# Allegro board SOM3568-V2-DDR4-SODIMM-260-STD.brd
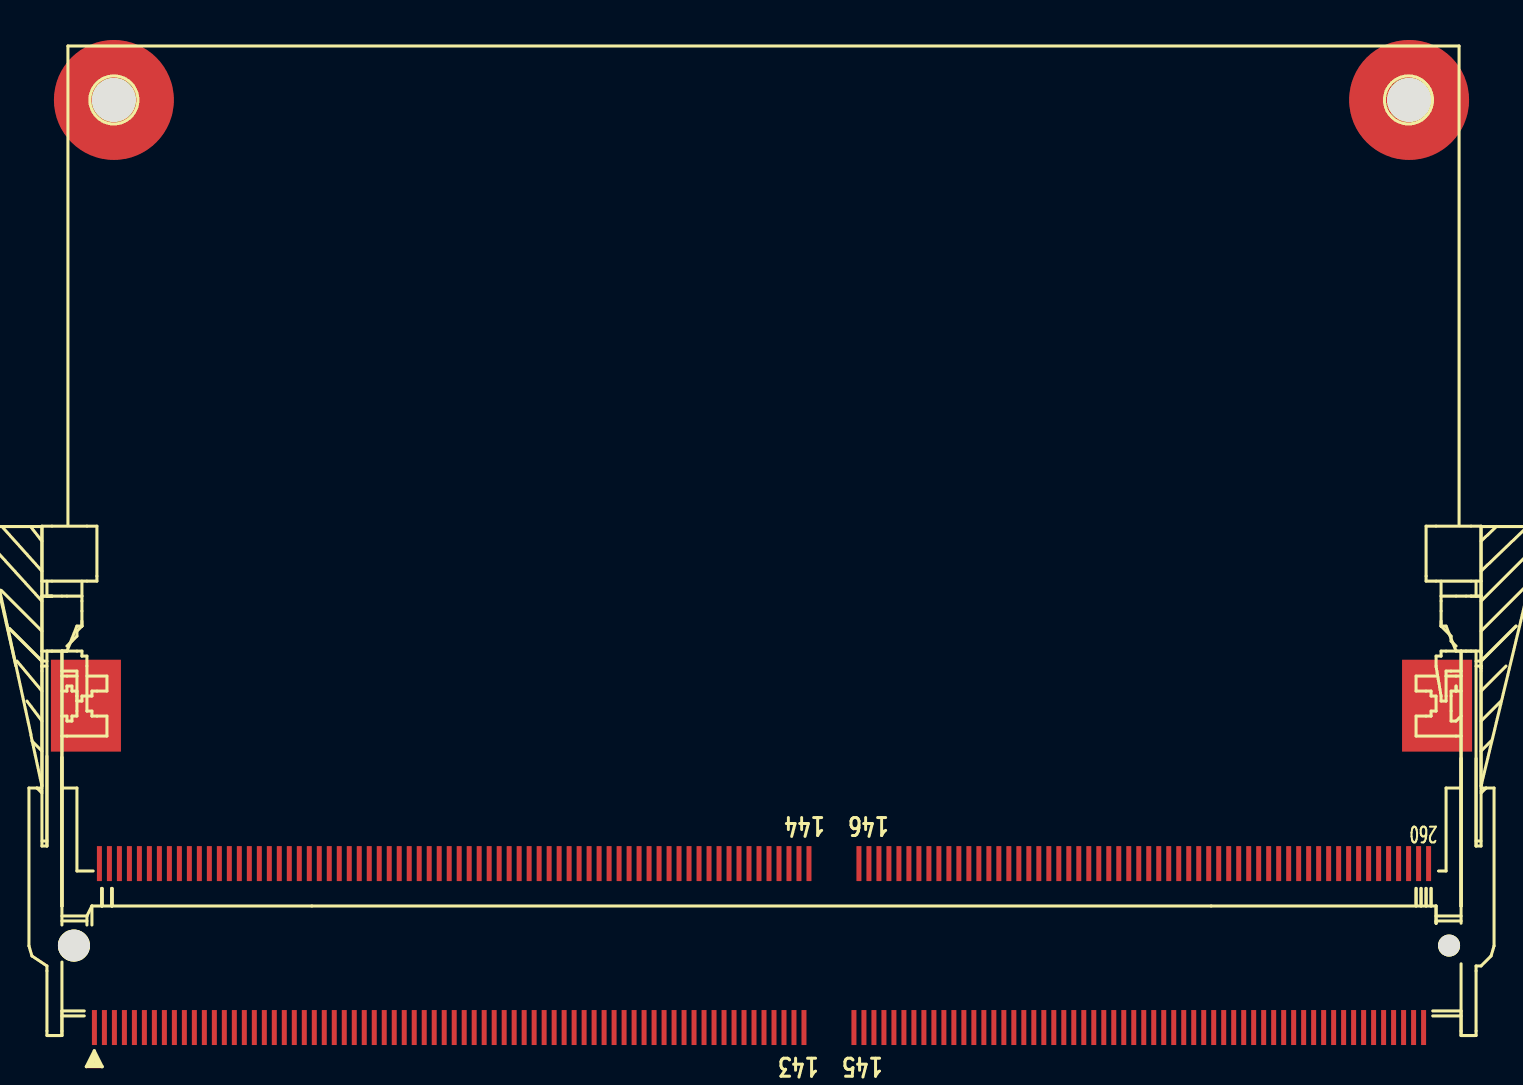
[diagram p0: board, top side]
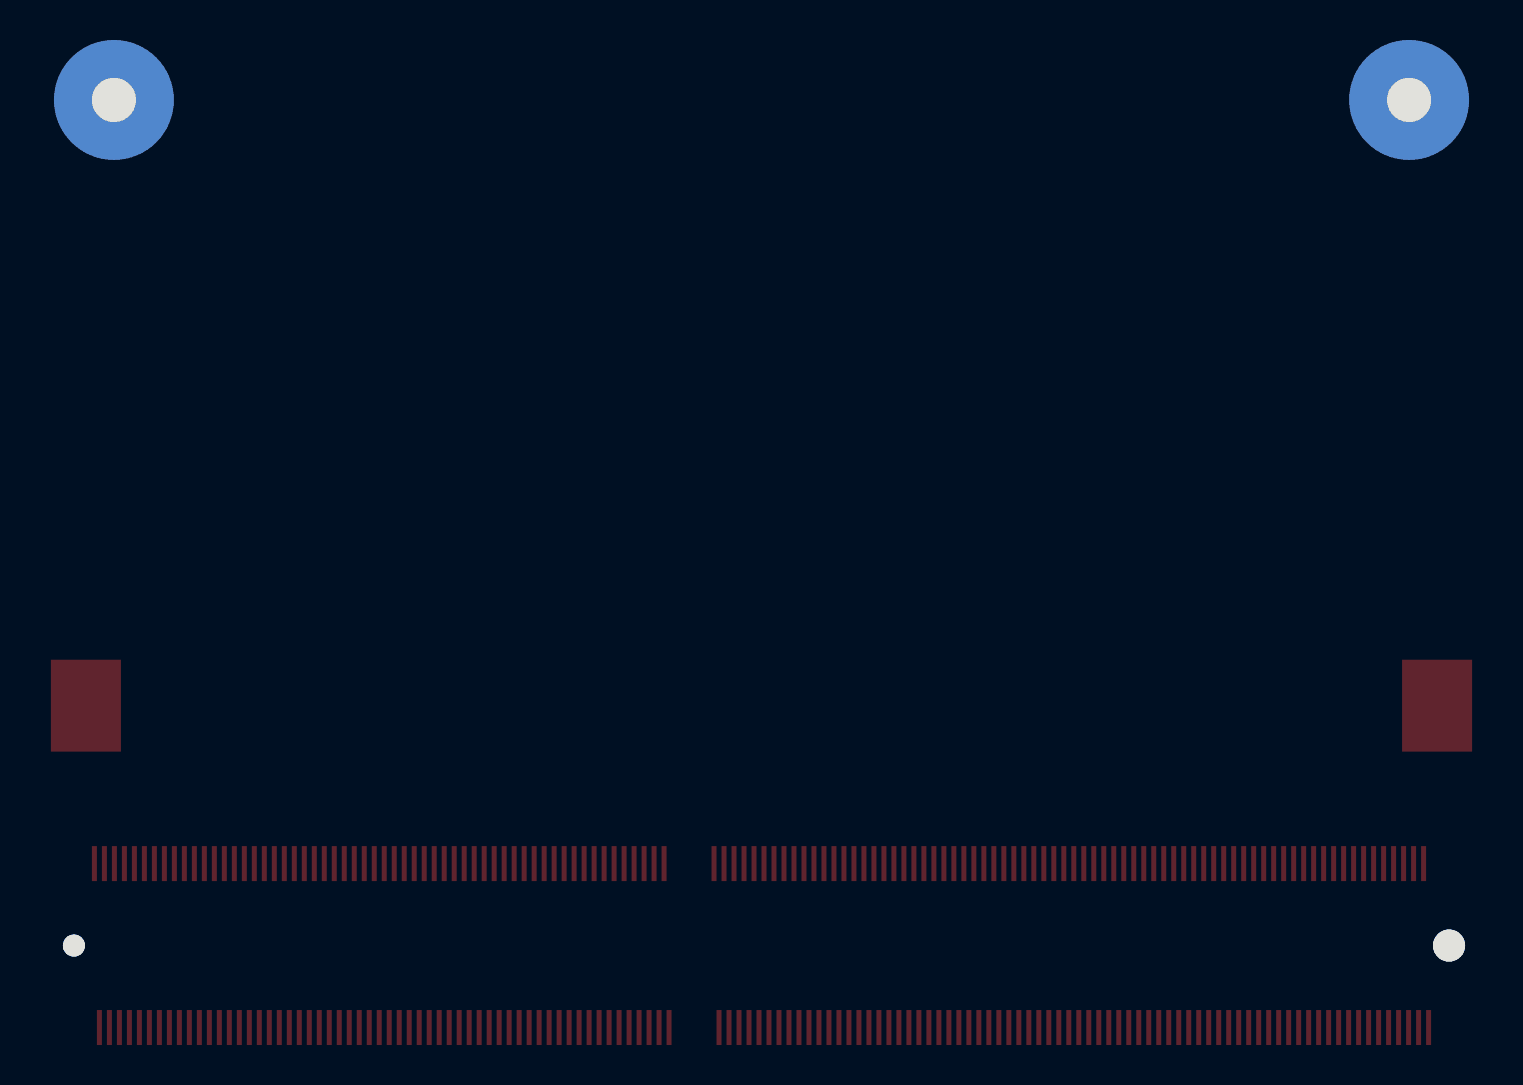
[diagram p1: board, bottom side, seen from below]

No outline. copper layers: TOP, VCC, GND, BOTTOM. Coordinates in mm from the lowest, leftmost part position.

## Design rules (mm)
net group DIFFPAIR0: nets HDMI_TX_D2N HDMI_TX_D2P
net group DIFFPAIR1: nets HDMI_TX_D2N_ HDMI_TX_D2P_
net group DIFFPAIR2: nets HDMI_TX_D1N_ HDMI_TX_D1P_
net group DIFFPAIR3: nets HDMI_TX_D1N HDMI_TX_D1P
net group DIFFPAIR4: nets HDMI_TX_D0N_ HDMI_TX_D0P_
net group DIFFPAIR5: nets HDMI_TX_D0N HDMI_TX_D0P
net group DIFFPAIR6: nets HDMI_TX_CLKN_ HDMI_TX_CLKP_
net group DIFFPAIR7: nets HDMI_TX_CLKN HDMI_TX_CLKP
net group DIFFPAIR11: nets USB2_HOST3_DM USB2_HOST3_DP
net group DIFFPAIR41: nets USB3_HOST1_SSTXN USB3_HOST1_SSTXP
net group DIFFPAIR43: nets USB3_OTG0_SSTXN USB3_OTG0_SSTXP
net group DIFFPAIR44: nets USB3_OTG0_DM USB3_OTG0_DP
net group DIFFPAIR45: nets USB3_HOST1_DM USB3_HOST1_DP
net group DIFFPAIR47: nets USB3_HOST1_SSRXN USB3_HOST1_SSRXP
net group DIFFPAIR49: nets USB3_OTG0_SSRXN USB3_OTG0_SSRXP
net group DIFFPAIR71: nets USB2_HOST2_DM USB2_HOST2_DP
net group DIFFPAIR76: nets PHY0_MDI3+ PHY0_MDI3-
net group DIFFPAIR77: nets PHY0_MDI2+ PHY0_MDI2-
net group DIFFPAIR78: nets PHY0_MDI1+ PHY0_MDI1-
net group DIFFPAIR79: nets LAN0_B+ LAN0_B-
net group DIFFPAIR80: nets LAN0_C+ LAN0_C-
net group DIFFPAIR81: nets LAN0_D+ LAN0_D-
net group DIFFPAIR82: nets LAN0_A+ LAN0_A-
net group DIFFPAIR83: nets PHY0_MDI0+ PHY0_MDI0-
net group DIFFPAIR95: nets VOR+ VOR-
net group DIFFPAIR98: nets VON1 VOP1
net group DIFFPAIR99: nets MIPI_CSI_RX_D0N MIPI_CSI_RX_D0P
net group DIFFPAIR100: nets MIPI_CSI_RX_D1N MIPI_CSI_RX_D1P
net group DIFFPAIR101: nets MIPI_CSI_RX_D2N MIPI_CSI_RX_D2P
net group DIFFPAIR102: nets MIPI_CSI_RX_D3N MIPI_CSI_RX_D3P
net group DIFFPAIR103: nets MIPI_CSI_RX_CLK0N MIPI_CSI_RX_CLK0P
net group DIFFPAIR104: nets MIPI_CSI_D0N MIPI_CSI_D0P
net group DIFFPAIR105: nets MIPI_CSI_D1N MIPI_CSI_D1P
net group DIFFPAIR106: nets MIPI_CSI_D2N MIPI_CSI_D2P
net group DIFFPAIR107: nets MIPI_CSI_D3N MIPI_CSI_D3P
net group DIFFPAIR108: nets USB3_HOST1_DM_ USB3_HOST1_DP_
net group DIFFPAIR109: nets USB2_HOST2_DM_ USB2_HOST2_DP_
net group DIFFPAIR110: nets USB3_HOST1_SSRXN_ USB3_HOST1_SSRXP_
net group DIFFPAIR111: nets USB3_HOST1_SSTXN_ USB3_HOST1_SSTXP_
net group DIFFPAIR112: nets 4G_DM 4G_DP
net group DIFFPAIR113: nets LAN1_D+ LAN1_D-
net group DIFFPAIR114: nets LAN1_C+ LAN1_C-
net group DIFFPAIR115: nets LAN1_B+ LAN1_B-
net group DIFFPAIR116: nets LAN1_A+ LAN1_A-
net group DIFFPAIR117: nets PHY1_MDI3+ PHY1_MDI3-
net group DIFFPAIR118: nets PHY1_MDI2+ PHY1_MDI2-
net group DIFFPAIR119: nets PHY1_MDI1+ PHY1_MDI1-
net group DIFFPAIR120: nets PHY1_MDI0+ PHY1_MDI0-
net group DIFFPAIR121: nets LVDS_TX0_CLKN LVDS_TX0_CLKP
net group DIFFPAIR122: nets LVDS_TX0_CLKN_ LVDS_TX0_CLKP_
net group DIFFPAIR123: nets LVDS_TX0_D2N_ LVDS_TX0_D2P_
net group DIFFPAIR124: nets LVDS_TX0_D2N LVDS_TX0_D2P
net group DIFFPAIR125: nets LVDS_TX0_D1N_ LVDS_TX0_D1P_
net group DIFFPAIR126: nets LVDS_TX0_D1N LVDS_TX0_D1P
net group DIFFPAIR127: nets LVDS_TX0_D0N LVDS_TX0_D0P
net group DIFFPAIR128: nets LVDS_TX0_D0N_ LVDS_TX0_D0P_
net group DIFFPAIR129: nets RS485_DM RS485_DP
net group DIFFPAIR130: nets RS485-A RS485-B
net group DIFFPAIR131: nets CAN0_H CAN0_L
net group DIFFPAIR132: nets CAN0H CAN0L
net group DIFFPAIR133: nets RS485-A_ RS485-B_
net group DIFFPAIR134: nets CAN0H_ CAN0L_
net group DIFFPAIR135: nets CAN1H_ CAN1L_
net group DIFFPAIR136: nets CAN1H CAN1L
net group DIFFPAIR137: nets CAN1_H CAN1_L
net group DIFFPAIR138: nets CAN2_H CAN2_L
net group DIFFPAIR139: nets CAN2H CAN2L
net group DIFFPAIR140: nets CAN0_RX_M0_ CAN0_TX_M0_
net group DIFFPAIR141: nets CAN1_RX_M1_ CAN1_TX_M1_
net group DIFFPAIR142: nets CAN2_RX_M0- CAN2_TX_M0-
net group DIFFPAIR143: nets RS232-RX RS232-TX
net group DIFFPAIR144: nets RS232-RX_ RS232-TX_
net group DIFFPAIR145: nets N69526109 N69526111
net group DIFFPAIR146: nets MIPI_CSI_CLK1N MIPI_CSI_CLK1P
net group DIFFPAIR147: nets MIPI_CSI_RX_CLK1N MIPI_CSI_RX_CLK1P
net group DIFFPAIR148: nets MIPI_CSI_CLK0N MIPI_CSI_CLK0P
net group DIFFPAIR149: nets LVDS_TX0_D3N LVDS_TX0_D3P
net group DIFFPAIR150: nets LVDS_TX0_D3N_ LVDS_TX0_D3P_
net group DIFFPAIR151: nets USB3_OTG0_DM_ USB3_OTG0_DP_
net group DIFFPAIR152: nets CAN2H_ CAN2L_
net group GND: nets GND
net group PWR-20: nets VDD_RTC
net group SD-12: nets SD_CMD SD_D0 SD_D1 SD_D2 SD_D3

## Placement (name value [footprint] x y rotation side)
J3  ATMD097-AED4S-5F  [DDR4-SODIMM-260P-STD]  0 0 0 top

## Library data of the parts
J3 = ATMD097-AED4S-5F_5

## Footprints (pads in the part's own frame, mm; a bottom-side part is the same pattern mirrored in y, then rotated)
DDR4-SODIMM-260P-STD
  round 1.6 hole 1.6 unplated: (0,0)
  round 1.1 hole 1.1 unplated: (68.8,0)
  rect 0.25x1.75 smd: 1(1.025,-4.1) 2(1.275,4.1) 3(1.525,-4.1) 4(1.775,4.1) 5(2.025,-4.1) 6(2.275,4.1) 7(2.525,-4.1) 8(2.775,4.1) 9(3.025,-4.1) 10(3.275,4.1) 11(3.525,-4.1) 12(3.775,4.1) 13(4.025,-4.1) 14(4.275,4.1) 15(4.525,-4.1) 16(4.775,4.1) 17(5.025,-4.1) 18(5.275,4.1) 19(5.525,-4.1) 20(5.775,4.1) 21(6.025,-4.1) 22(6.275,4.1) 23(6.525,-4.1) 24(6.775,4.1) 25(7.025,-4.1) 26(7.275,4.1) 27(7.525,-4.1) 28(7.775,4.1) 29(8.025,-4.1) 30(8.275,4.1) 31(8.525,-4.1) 32(8.775,4.1) 33(9.025,-4.1) 34(9.275,4.1) 35(9.525,-4.1) 36(9.775,4.1) 37(10.025,-4.1) 38(10.275,4.1) 39(10.525,-4.1) 40(10.775,4.1) 41(11.025,-4.1) 42(11.275,4.1) 43(11.525,-4.1) 44(11.775,4.1) 45(12.025,-4.1) 46(12.275,4.1) 47(12.525,-4.1) 48(12.775,4.1) 49(13.025,-4.1) 50(13.275,4.1) 51(13.525,-4.1) 52(13.775,4.1) 53(14.025,-4.1) 54(14.275,4.1) 55(14.525,-4.1) 56(14.775,4.1) 57(15.025,-4.1) 58(15.275,4.1) 59(15.525,-4.1) 60(15.775,4.1) 61(16.025,-4.1) 62(16.275,4.1) 63(16.525,-4.1) 64(16.775,4.1) 65(17.025,-4.1) 66(17.275,4.1) 67(17.525,-4.1) 68(17.775,4.1) 69(18.025,-4.1) 70(18.275,4.1) 71(18.525,-4.1) 72(18.775,4.1) 73(19.025,-4.1) 74(19.275,4.1) 75(19.525,-4.1) 76(19.775,4.1) 77(20.025,-4.1) 78(20.275,4.1) 79(20.525,-4.1) 80(20.775,4.1) 81(21.025,-4.1) 82(21.275,4.1) 83(21.525,-4.1) 84(21.775,4.1) 85(22.025,-4.1) 86(22.275,4.1) 87(22.525,-4.1) 88(22.775,4.1) 89(23.025,-4.1) 90(23.275,4.1) 91(23.525,-4.1) 92(23.775,4.1) 93(24.025,-4.1) 94(24.275,4.1) 95(24.525,-4.1) 96(24.775,4.1) 97(25.025,-4.1) 98(25.275,4.1) 99(25.525,-4.1) 100(25.775,4.1) 101(26.025,-4.1) 102(26.275,4.1) 103(26.525,-4.1) 104(26.775,4.1) 105(27.025,-4.1) 106(27.275,4.1) 107(27.525,-4.1) 108(27.775,4.1) 109(28.025,-4.1) 110(28.275,4.1) 111(28.525,-4.1) 112(28.775,4.1) 113(29.025,-4.1) 114(29.275,4.1) 115(29.525,-4.1) 116(29.775,4.1) 117(30.025,-4.1) 118(30.275,4.1) 119(30.525,-4.1) 120(30.775,4.1) 121(31.025,-4.1) 122(31.275,4.1) 123(31.525,-4.1) 124(31.775,4.1) 125(32.025,-4.1) 126(32.275,4.1) 127(32.525,-4.1) 128(32.775,4.1) 129(33.025,-4.1) 130(33.275,4.1) 131(33.525,-4.1) 132(33.775,4.1) 133(34.025,-4.1) 134(34.275,4.1) 135(34.525,-4.1) 136(34.775,4.1) 137(35.025,-4.1) 138(35.275,4.1) 139(35.525,-4.1) 140(35.775,4.1) 141(36.025,-4.1) 142(36.275,4.1) 143(36.525,-4.1) 144(36.775,4.1) 145(39.025,-4.1) 146(39.275,4.1) 147(39.525,-4.1) 148(39.775,4.1) 149(40.025,-4.1) 150(40.275,4.1) 151(40.525,-4.1) 152(40.775,4.1) 153(41.025,-4.1) 154(41.275,4.1) 155(41.525,-4.1) 156(41.775,4.1) 157(42.025,-4.1) 158(42.275,4.1) 159(42.525,-4.1) 160(42.775,4.1) 161(43.025,-4.1) 162(43.275,4.1) 163(43.525,-4.1) 164(43.775,4.1) 165(44.025,-4.1) 166(44.275,4.1) 167(44.525,-4.1) 168(44.775,4.1) 169(45.025,-4.1) 170(45.275,4.1) 171(45.525,-4.1) 172(45.775,4.1) 173(46.025,-4.1) 174(46.275,4.1) 175(46.525,-4.1) 176(46.775,4.1) 177(47.025,-4.1) 178(47.275,4.1) 179(47.525,-4.1) 180(47.775,4.1) 181(48.025,-4.1) 182(48.275,4.1) 183(48.525,-4.1) 184(48.775,4.1) 185(49.025,-4.1) 186(49.275,4.1) 187(49.525,-4.1) 188(49.775,4.1) 189(50.025,-4.1) 190(50.275,4.1) 191(50.525,-4.1) 192(50.775,4.1) 193(51.025,-4.1) 194(51.275,4.1) 195(51.525,-4.1) 196(51.775,4.1) 197(52.025,-4.1) 198(52.275,4.1) 199(52.525,-4.1) 200(52.775,4.1) 201(53.025,-4.1) 202(53.275,4.1) 203(53.525,-4.1) 204(53.775,4.1) 205(54.025,-4.1) 206(54.275,4.1) 207(54.525,-4.1) 208(54.775,4.1) 209(55.025,-4.1) 210(55.275,4.1) 211(55.525,-4.1) 212(55.775,4.1) 213(56.025,-4.1) 214(56.275,4.1) 215(56.525,-4.1) 216(56.775,4.1) 217(57.025,-4.1) 218(57.275,4.1) 219(57.525,-4.1) 220(57.775,4.1) 221(58.025,-4.1) 222(58.275,4.1) 223(58.525,-4.1) 224(58.775,4.1) 225(59.025,-4.1) 226(59.275,4.1) 227(59.525,-4.1) 228(59.775,4.1) 229(60.025,-4.1) 230(60.275,4.1) 231(60.525,-4.1) 232(60.775,4.1) 233(61.025,-4.1) 234(61.275,4.1) 235(61.525,-4.1) 236(61.775,4.1) 237(62.025,-4.1) 238(62.275,4.1) 239(62.525,-4.1) 240(62.775,4.1) 241(63.025,-4.1) 242(63.275,4.1) 243(63.525,-4.1) 244(63.775,4.1) 245(64.025,-4.1) 246(64.275,4.1) 247(64.525,-4.1) 248(64.775,4.1) 249(65.025,-4.1) 250(65.275,4.1) 251(65.525,-4.1) 252(65.775,4.1) 253(66.025,-4.1) 254(66.275,4.1) 255(66.525,-4.1) 256(66.775,4.1) 257(67.025,-4.1) 258(67.275,4.1) 259(67.525,-4.1) 260(67.775,4.1)
  rect 3.505x4.597 smd: N1(0.6,12) N2(68.2,12)
  round 6 hole 2.2: N3(2,42.3) N4(66.8,42.3)

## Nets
GND: J3.15(GND1) J3.30(GND2) J3.31(GND3) J3.51(GND4) J3.56(GND5) J3.69(GND6) J3.84(GND7) J3.95(GND8) J3.106(GND9) J3.121(GND10) J3.145(GND11) J3.151(GND12) J3.158(GND13) J3.165(GND14) J3.180(GND15) J3.194(GND16) J3.195(GND17) J3.214(GND18) J3.217(GND19) J3.240(GND20) J3.254(GND21) J3.256(GND22) J3.258(GND23) J3.260(GND24) J3.N3 J3.N4
VCC3V3_SD: J3.210(VCC3V3_SD_OUT)
VCC5V0_M: J3.253(VCC5V0_SYS1) J3.255(VCC5V0_SYS2) J3.257(VCC5V0_SYS3) J3.259(VCC5V0_SYS4)
VCC_1V8: J3.237(VCC_1V8_OUT)
VCC_3V3: J3.245(VCC_3V3_OUT)
4G_PWREN_H_GPIO0_D5: J3.11(GPIO0_D5_D/SARADC_VIN6)
BT_REG_ON_H_GPIO3_A0: J3.71(LCDC_CLK/VOP_BT656_CLK_M0/SPI2_)
BT_RST_L_GPIO4_C4: J3.140(EDP_HPDIN_M0/SPDIF_TX_M2/SATA2_)
BT_WAKE_HOST_H_GPIO3_A1: J3.67(LCDC_D8/VOP_BT1120_D0/SPI1_CS0_)
CAM_CLKOUT0: J3.108(REFCLK_OUT/GPIO0_A0_D)
CAN0_RX_M0: J3.148(I2C1_SDA/CAN0_RX_M0/PCIE20_BUTT)
CAN0_TX_M0: J3.146(I2C1_SCL/CAN0_TX_M0/PCIE30X1_BU)
CAN1_RX_M1: J3.136(PWM14_M1/SPI3_CLK_M1/CAN1_RX_M1)
CAN1_TX_M1: J3.138(PWM15_IR_M1/SPI3_MOSI_M1/CAN1_T)
CAN2_RX_M0: J3.44(I2C2_SDA_M1/EBC_GDSP/CAN2_RX_M0)
CAN2_TX_M0: J3.46(I2C2_SCL_M1/EBC_SDSHR/CAN2_TX_M)
CIF_CLKOUT_SOC: J3.52(CIF_CLKOUT/EBC_GDCLK/PWM11_IR_M)
DOG_GPIO0_C2: J3.124(PWM3_IR/EDP_HPDIN_M1/PCIE30X1_W)
ETH0_REFCLKO_25M: J3.228(I2S2_MCLK_M0/ETH0_REFCLKO_25M/U)
ETH1_REFCLKO_25M_M0: J3.53(LCDC_D15/VOP_BT1120_D6/ETH1_REF)
EXT_EN: J3.249(EXT_EN)
GMAC0_INT/PMEB_GPIO2_D2: J3.83(LCDC_D2/VOP_BT656_D2_M0/SPI0_CS)
GMAC0_MCLKINOUT: J3.230(I2S2_SCLK_TX_M0/GMAC0_MCLKINOUT)
GMAC0_MDC: J3.232(I2S2_LRCK_TX_M0/GMAC0_MDC/UART9)
GMAC0_MDIO: J3.234(I2S2_SDO_M0/GMAC0_MDIO/UART9_CT)
GMAC0_RSTN_GPIO2_D3: J3.81(LCDC_D3/VOP_BT656_D3_M0/SPI0_CL)
GMAC0_RXCLK: J3.223(SDMMC1_D2/GMAC0_RXCLK/UART7_RX_)
GMAC0_RXD0: J3.222(GMAC0_RXD0/UART1_CTSN_M0/SPI1_M)
GMAC0_RXD1: J3.224(I2S2_SCLK_RX_M0/GMAC0_RXD1/UART)
GMAC0_RXD2: J3.219(SDMMC1_D0/GMAC0_RXD2/UART6_RX_M)
GMAC0_RXD3: J3.221(SDMMC1_D1/GMAC0_RXD3/UART6_TX_M)
GMAC0_RXDV_CRS: J3.226(I2S2_LRCK_RX_M0/GMAC0_RXDV_CRS/)
GMAC0_TXCLK: J3.229(SDMMC1_CLK/GMAC0_TXCLK/UART9_TX)
GMAC0_TXD0: J3.216(GMAC0_TXD0/UART1_RX_M0/GPIO2_B3)
GMAC0_TXD1: J3.218(GMAC0_TXD1/UART1_TX_M0/GPIO2_B4)
GMAC0_TXD2: J3.225(SDMMC1_D3/GMAC0_TXD2/UART7_TX_M)
GMAC0_TXD3: J3.227(SDMMC1_CMD/GMAC0_TXD3/UART9_RX_)
GMAC0_TXEN: J3.220(GMAC0_TXEN/UART1_RTSN_M0/SPI1_C)
GMAC1_INT/PMEB_GPIO3_A7: J3.55(LCDC_D14/VOP_BT1120_D5/GMAC1_RX)
GMAC1_MCLKINOUT_M1: J3.54(CIF_CLKIN/EBC_SDCLK/GMAC1_MCLKI)
GMAC1_MDC_M1: J3.48(CIF_HREF/EBC_SDLE/GMAC1_MDC_M1/)
GMAC1_MDIO_M1: J3.50(CIF_VSYNC/EBC_SDOE/GMAC1_MDIO_M)
GMAC1_RSTN_GPIO3_B5: J3.74(LCDC_D20/VOP_BT1120_D11/GMAC1_T)
GMAC1_RXCLK_M1: J3.45(CIF_D13/EBC_SDDO13/GMAC1_RXCLK_)
GMAC1_RXD0_M1: J3.34(CAM_CLKOUT0/EBC_SDCE1/GMAC1_RXD)
GMAC1_RXD1_M1: J3.36(CAM_CLKOUT1/EBC_SDCE2/GMAC1_RXD)
GMAC1_RXD2_M1: J3.41(CIF_D11/EBC_SDDO11/GMAC1_RXD2_M)
GMAC1_RXD3_M1: J3.43(CIF_D12/EBC_SDDO12/GMAC1_RXD3_M)
GMAC1_RXDV_CRS_M1: J3.38(ISP_PRELIGHT_TRIG/EBC_SDCE3/GMA)
GMAC1_TXCLK_M1: J3.39(CIF_D10/EBC_SDDO10/GMAC1_TXCLK_)
GMAC1_TXD0_M1: J3.47(CIF_D14/EBC_SDDO14/GMAC1_TXD0_M)
GMAC1_TXD1_M1: J3.49(CIF_D15/EBC_SDDO15/GMAC1_TXD1_M)
GMAC1_TXD2_M1: J3.35(CIF_D8/EBC_SDDO8/GMAC1_TXD2_M1/)
GMAC1_TXD3_M1: J3.37(CIF_D9/EBC_SDDO9/GMAC1_TXD3_M1/)
GMAC1_TXEN_M1: J3.32(ISP_FLASHTRIGOUT/EBC_SDCE0/GMAC)
GPS_POWER_H_GPIO3_C2: J3.64(LCDC_VSYNC/VOP_BT1120_D14/SPI1_)
HDMI_TX_CLKN: J3.147(HDMI_TX_CLKN)
HDMI_TX_CLKP: J3.149(HDMI_TX_CLKP)
HDMI_TX_D0N: J3.155(HDMI_TX_D0N)
HDMI_TX_D0P: J3.153(HDMI_TX_D0P)
HDMI_TX_D1N: J3.159(HDMI_TX_D1N)
HDMI_TX_D1P: J3.157(HDMI_TX_D1P)
HDMI_TX_D2N: J3.163(HDMI_TX_D2N)
HDMI_TX_D2P: J3.161(HDMI_TX_D2P)
HDMI_TX_HPDIN: J3.143(HDMI_TX_HPDIN)
HDMITX_CEC_M0: J3.89(HDMITX_CEC_M0/SPI3_CS1_M1/GPIO4)
HEATER_DIS_GPIO0_C6: J3.132(PWM7_IR/SPI0_CS0_M0/PCIE30X2_PE)
HOST_WAKE_BT_H_GPIO3_A2: J3.65(LCDC_D9/VOP_BT1120_D1/GMAC1_TXD)
HP_SNS: J3.244(HP_SNS)
HPL_OUT: J3.242(HPL_OUT)
HPR_OUT: J3.246(HPR_OUT)
HW_ADDR1_GPIO2_D1: J3.85(LCDC_D1/VOP_BT656_D1_M0/SPI0_MO)
HW_ADDR2_GPIO2_D0: J3.87(LCDC_D0/VOP_BT656_D0_M0/SPI0_MI)
HW_ADDR3_GPIO3_C1: J3.66(LCDC_HSYNC/VOP_BT1120_D13/SPI1_)
HW_ADDR4_GPIO2_D7: J3.73(LCDC_D7/VOP_BT656_D7_M0/SPI2_MI)
I2C3_SCL_M0: J3.156(I2C3_SCL_M0/UART3_TX_M0/CAN1_TX)
I2C3_SDA_M0: J3.154(I2C3_SDA_M0/UART3_RX_M0/CAN1_RX)
I2C4_SCL_M0: J3.42(I2C4_SCL_M0/EBC_GDOE/ETH1_REFCL)
I2C4_SDA_M0: J3.40(I2C4_SDA_M0/EBC_VCOM/GMAC1_RXER)
I2C5_SCL-HDMI: J3.93(HDMITX_SCL/I2C5_SCL_M1/GPIO4_C7)
I2C5_SCL_M0: J3.78(LCDC_D18/VOP_BT1120_D9/GMAC1_RX)
I2C5_SDA-HDMI: J3.91(HDMITX_SDA/I2C5_SDA_M1/GPIO4_D0)
I2C5_SDA_M0: J3.76(LCDC_D19/VOP_BT1120_D10/GMAC1_R)
IR_PDN_H_GPIO1_D1: J3.12(FSPI_D0/FLASH_RDY/GPIO1_D1_U)
IR_RST_L_GPIO1_D2: J3.14(FSPI_D1/FLASH_RDN/GPIO1_D2_U)
LCD_RSTN_GPIO4_D2: J3.13(GPIO4_D2_D/SARADC_VIN7)
LVDS_TX0_BL_EN: J3.134(HDMITX_CEC_M1/PWM0_M1/UART0_CTS)
LVDS_TX0_BL_PWM4: J3.126(PWM4/VOP_PWM_M0/PCIE30X1_PERSTN)
LVDS_TX0_CLKN: J3.133(MIPI_DSI_TX0_CLKN/LVDS_TX0_CLKN)
LVDS_TX0_CLKP: J3.131(MIPI_DSI_TX0_CLKP/LVDS_TX0_CLKP)
LVDS_TX0_D0N: J3.141(MIPI_DSI_TX0_D0N/LVDS_TX0_D0N)
LVDS_TX0_D0P: J3.139(MIPI_DSI_TX0_D0P/LVDS_TX0_D0P)
LVDS_TX0_D1N: J3.137(MIPI_DSI_TX0_D1N/LVDS_TX0_D1N)
LVDS_TX0_D1P: J3.135(MIPI_DSI_TX0_D1P/LVDS_TX0_D1P)
LVDS_TX0_D2N: J3.129(MIPI_DSI_TX0_D2N/LVDS_TX0_D2N)
LVDS_TX0_D2P: J3.127(MIPI_DSI_TX0_D2P/LVDS_TX0_D2P)
LVDS_TX0_D3N: J3.125(MIPI_DSI_TX0_D3N/LVDS_TX0_D3N)
LVDS_TX0_D3P: J3.123(MIPI_DSI_TX0_D3P/LVDS_TX0_D3P)
MIC1_INN: J3.250(MIC1_INN)
MIC1_INP: J3.248(MIC1_INP)
MIPI_CSI_RX_CLK0N: J3.103(MIPI_CSI_RX_CLK0N)
MIPI_CSI_RX_CLK0P: J3.101(MIPI_CSI_RX_CLK0P)
MIPI_CSI_RX_CLK1N: J3.99(MIPI_CSI_RX_CLK1N)
MIPI_CSI_RX_CLK1P: J3.97(MIPI_CSI_RX_CLK1P)
MIPI_CSI_RX_D0N: J3.119(MIPI_CSI_RX_D0N)
MIPI_CSI_RX_D0P: J3.117(MIPI_CSI_RX_D0P)
MIPI_CSI_RX_D1N: J3.115(MIPI_CSI_RX_D1N)
MIPI_CSI_RX_D1P: J3.113(MIPI_CSI_RX_D1P)
MIPI_CSI_RX_D2N: J3.111(MIPI_CSI_RX_D2N)
MIPI_CSI_RX_D2P: J3.109(MIPI_CSI_RX_D2P)
MIPI_CSI_RX_D3N: J3.107(MIPI_CSI_RX_D3N)
MIPI_CSI_RX_D3P: J3.105(MIPI_CSI_RX_D3P)
NET_LED_GPIO4_C6: J3.144(PWM13_M1/SPI3_CS0_M1/SATA0_ACT_)
NTC_SARADC_VIN3: J3.5(SARADC_VIN3)
RGB_PDN_H_GPIO1_D3: J3.18(FSPI_D3/FLASH_CS1N/GPIO1_D4_U)
RGB_RST_H_GPIO1_D4: J3.20(FSPI_CS0N/FLASH_CS0N/GPIO1_D3_U)
RK809-CLK32K: J3.247(RK809-CLK32K)
RK809_PWRON: J3.251(RK809_PWRON)
RK809_VDC: J3.252(RK809_VDC)
RS485_DIR_GPIO3_C3: J3.62(LCDC_DEN/VOP_BT1120_D15/SPI1_CL)
SARADC_VIN0_KEY/RECOVERY: J3.1(SARADC_VIN0_KEY/RECOVERY)
SDMMC0_CLK: J3.206(SDMMC0_CLK/TEST_CLKOUT/UART5_TX)
SDMMC0_CMD: J3.204(SDMMC0_CMD/PWM10_M1/UART5_RX_M0)
SDMMC0_D0: J3.196(SDMMC0_D0/UART2_TX_M1/UART6_TX_)
SDMMC0_D1: J3.198(SDMMC0_D1/UART2_RX_M1/UART6_RX_)
SDMMC0_D2: J3.200(SDMMC0_D2/ARMJTAG_TCK/UART5_CTS)
SDMMC0_D3: J3.202(SDMMC0_D3/ARMJTAG_TMS/UART5_RTS)
SDMMC0_DET_L: J3.208(SDMMC0_DET/SATA_CP_DET/PCIE30X1)
SDMMC2_CLK_M0: J3.27(CIF_D5/EBC_SDDO5/SDMMC2_CLK_M0/)
SDMMC2_CMD_M0: J3.25(CIF_D4/EBC_SDDO4/SDMMC2_CMD_M0/)
SDMMC2_D0_M0: J3.17(CIF_D0/EBC_SDDO0/SDMMC2_D0_M0/I)
SDMMC2_D1_M0: J3.19(CIF_D1/EBC_SDDO1/SDMMC2_D1_M0/I)
SDMMC2_D2_M0: J3.21(CIF_D2/EBC_SDDO2/SDMMC2_D2_M0/I)
SDMMC2_D3_M0: J3.23(CIF_D3/EBC_SDDO3/SDMMC2_D3_M0/I)
SPK_CTL_H_GPIO3_A5: J3.59(LCDC_D12/VOP_BT1120_D4/GMAC1_RX)
SPK_MUTE_H_GPIO3_A4: J3.61(LCDC_D11/VOP_BT1120_D3/GMAC1_RX)
SYS_LED_GPIO4_C5: J3.142(PWM12_M1/SPI3_MISO_M1/SATA1_ACT)
SYS_RESETN: J3.235(SYS_RESETN)
TP_INT_L_GPIO0_B5: J3.150(I2C2_SCL_M0/SPI0_CLK_M0/PCIE20_)
TP_RST_L_GPIO0_B6: J3.152(I2C2_SDA_M0/SPI0_MOSI_M0/PCIE20)
UART2_RX_M0: J3.116(UART2_RX_M0/GPIO_D0_U)
UART2_TX_M0: J3.118(UART2_TX_M0/GPIO_D1_U)
UART3_RX_M1: J3.68(LCDC_D23/PWM13_M0/GMAC1_MCLKINO)
UART3_TX_M1: J3.70(LCDC_D22/PWM12_M0/GMAC1_TXEN_M0)
UART4_RX_M1: J3.82(LCDC_D16/VOP_BT1120_D7/GMAC1_RX)
UART4_TX_M1: J3.80(LCDC_D17/VOP_BT1120_D8/GMAC1_RX)
UART7_RX_M1: J3.58(PWM15_IR_M0/SPDIF_TX_M1/GMAC1_M)
UART7_TX_M1: J3.60(PWM14_M0/VOP_PWM_M1/GMAC1_MDC_M)
UART8_CTSN_M0: J3.233(SDMMC1_DET/I2C4_SCL_M1/UART8_CT)
UART8_RTSN_M0: J3.231(SDMMC1_PWREN/I2C4_SDA_M1/UART8_)
UART8_RX_M0: J3.238(CLK32K_OUT1/UART8_RX_M0/SPI1_CS)
UART8_TX_M0: J3.236(I2S2_SDI_M0/GMAC0_RXER/UART8_TX)
USB2_HOST2_DM: J3.28(USB2_HOST2_DM)
USB2_HOST2_DP: J3.26(USB2_HOST2_DP)
USB2_HOST2_PWREN_H_GPIO0_A6: J3.110(GPU_PWREN/SATA_CP_POD/PCIE30X2_)
USB2_HOST3_DM: J3.24(USB2_HOST3_DM)
USB2_HOST3_DP: J3.22(USB2_HOST3_DP)
USB3_HOST1_DM: J3.169(USB3_HOST1_DM)
USB3_HOST1_DP: J3.167(USB3_HOST1_DP)
USB3_HOST1_PWREN_H_GPIO0_D4: J3.9(GPIO0_D4_D/SARADC_VIN5)
USB3_HOST1_SSRXN: J3.175(USB3_HOST1_SSRXN/SATA1_RXN/QSGM)
USB3_HOST1_SSRXP: J3.177(USB3_HOST1_SSRXP/SATA1_RXP/QSGM)
USB3_HOST1_SSTXN: J3.171(USB3_HOST1_SSTXN/SATA1_TXN/QSGM)
USB3_HOST1_SSTXP: J3.173(USB3_HOST1_SSTXP/SATA1_TXP/QSGM)
USB3_OTG0_DM: J3.189(USB3_OTG0_DM)
USB3_OTG0_DP: J3.187(USB3_OTG0_DP)
USB3_OTG0_ID: J3.193(USB3_OTG0_ID)
USB3_OTG0_SSRXN: J3.183(USB3_OTG0_SSRXN/SATA0_RXN)
USB3_OTG0_SSRXP: J3.185(USB3_OTG0_SSRXP/SATA0_RXP)
USB3_OTG0_SSTXN: J3.179(USB3_OTG0_SSTXN/SATA0_TXN)
USB3_OTG0_SSTXP: J3.181(USB3_OTG0_SSTXP/SATA0_TXP)
USB3_OTG0_VBUSDET: J3.191(USB3_OTG0_VBUSDET)
USB_OTG_PWREN_H_GPIO0_A5: J3.212(SDMMC0_PWREN/SATA_MP_SWITCH/PCI)
USER_LED1_GPIO0_C5: J3.130(PWM6/SPI0_MISO_M0/PCIE30X2_WAKE)
USER_LED2_GPIO1_D0: J3.10(FSPI_CLK/FLASH_ALE/GPIO1_D0_D)
WIFI_PWREN_L_GPIO0_B7: J3.114(PWM0-M0/CPUAVS/GPIO0_B7_D)
WIFI_REG_ON_H_GPIO3_D5: J3.33(CIF_D7/EBC_SDDO7/SDMMC2_PWREN_M)
WIFI_WAKE_HOST_H_GPIO3_D4: J3.29(CIF_D6/EBC_SDDO6/SDMMC2_DET_M0/)

Pads without a net: J3 2 3 4 6 7 8 16 57 63 72 75 77 79 86 88 90 92 94 96 98 100 102 104 112 120 122 128 160 162 164 166 168 170 172 174 176 178 182 184 186 188 190 192 197 199 201 203 205 207 209 211 213 215 239 241 243 N1 N2
